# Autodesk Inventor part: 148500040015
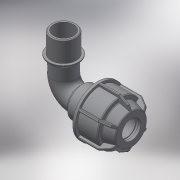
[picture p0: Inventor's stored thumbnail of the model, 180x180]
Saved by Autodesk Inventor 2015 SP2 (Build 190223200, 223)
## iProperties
Created: 2017-08
Part Number: 148500040015
Material: Generic
Description: PLASSON L.14 90° ELBOW MALE ADAPTOR (SILVER) 40-1.1/2"
Document SubType Name: Modeling
Designer: KIM
Density: 1 g/cm^3
Appearance: Default
Author: KIM
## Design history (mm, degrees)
derived "148500.ipt"
feature "Solid1::148500.ipt"
feature "Solid2::148500.ipt"
tag "TaggingFeature1"
body "Solid1"
body "Solid2"
other parameters: "d2" = 62, "d4" = 15 deg, "d5" = 40.92, "d6" = 13.5036, "d10" = 73, "d16" = 40.8, "d17" = 3.1, "d22" = 64, "d24" = 3.1, "d25" = 65.7, "d26" = 54.75, "d27" = 3.1, "d28" = 135 deg, "d29" = 1.86, "d31" = 2, "d46" = 150 deg, "d49" = 3.65, "d50" = 0, "d58" = 1.2, "d61" = 360 deg, "d63" = 38, "d94" = 69, "d96" = 52.5833, "d97" = 22, "d98" = 35.85225, "d99" = 47.32497, "d100" = 135 deg, "d108" = 2, "d112" = 28.6, "d113" = 86, "d114" = 63.24, "d115" = 47.32497, "d116" = 45 deg, "d117" = 0, "d118" = 0, "d119" = 47.803, "d120" = 22, "d121" = 57.3636, "d122" = 23.1, "d123" = 1, "R_" = 47.803, "E_" = 73, "A_" = 86, "l_" = 62, "l_2" = 22, "A_1" = 69
